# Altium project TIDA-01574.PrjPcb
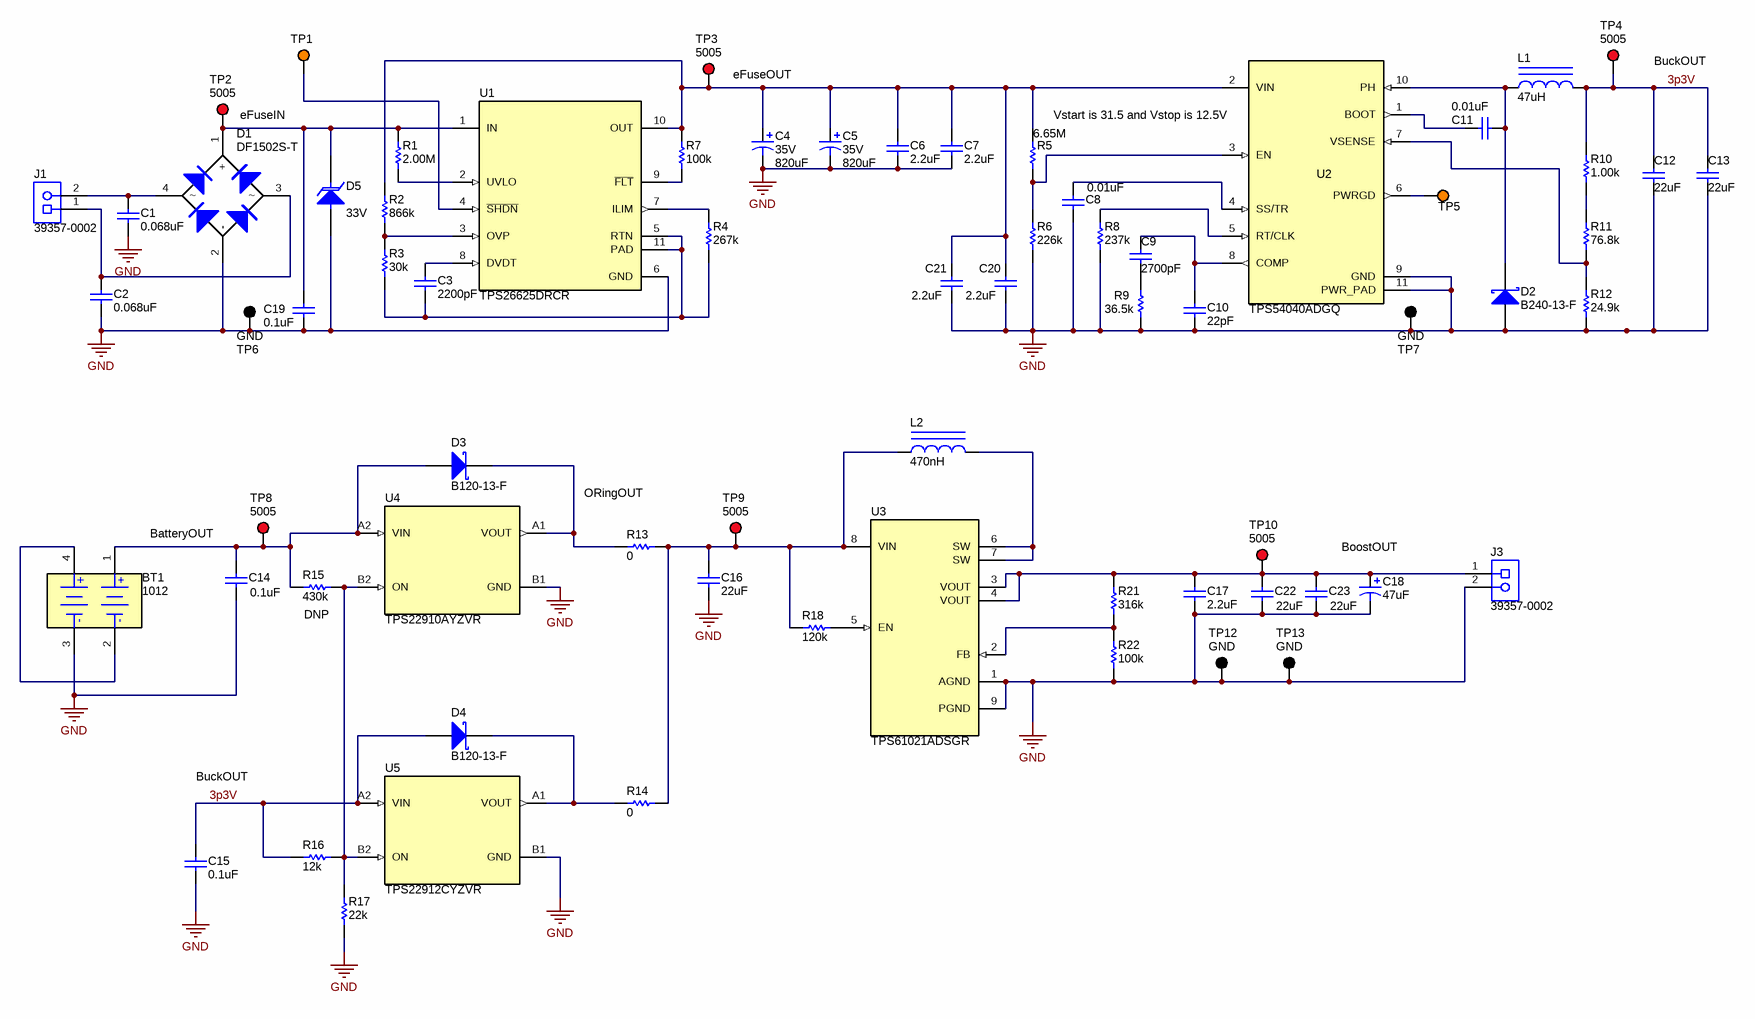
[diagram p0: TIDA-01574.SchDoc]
CopyrightYear: 2017; PCB_Layout: Mansur; PCB_Rev: E1; PRJ_Customer: Public Release; PRJ_Engineer: Karikalan Selvaraj; PRJ_Number: TIDA-01574; PRJ_Title: Power Stage Reference Design for Power Stealing Thermostat; SCH_Rev: E1; TechSupport: http://www.ti.com/support; TID: TIDA-01574
3 sheets, 83 parts. Net scope: global (net labels, ports and power ports of the same name join across sheets).
Board file: TIDA-01574.PcbDoc
Sheets:
  TIDA-01574.SchDoc
  TIDA-01574_CoverSheet.SchDoc
  TIDA-01574_Hardware.SchDoc

## Sheet TIDA-01574.SchDoc
size 431 x 279 mm; Date: Not shown in title block; ApprovedBy: Not shown in title block; CheckedBy: Not shown in title block; Author: Not shown in title block; CompanyName: Not shown in title block; Engineer: Not shown in title block; Organization: Not shown in title block; Address1: Not shown in title block; Address2: Not shown in title block; Address3: Not shown in title block; Address4: Not shown in title block; DocumentNumber: 1; Revision: Use project parameter SCH_Rev; SheetNumber: 2; SheetTotal: 3; PageSetup: Record=PageOptions¦CenterHorizontal=True¦CenterVertical=True¦PrintScale=1.00¦XCorrection=1.00¦YCorrection=1.00¦PrintKind=0¦BorderSize=5000000¦LeftOffset=0¦BottomOffset=0¦Orientation=2¦PaperLength=1000¦PaperWidth=1000¦Scale=100¦PaperSource=15¦PrintQuality=600¦MediaType=1¦DitherType=10¦PaperKind=Letter¦PrintScaleMode=1

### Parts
BT1  1012  [Keystone_1012]
C1  ValueDisplayed: 0.068uF  [0603]  (hidden comment: C1608X7S2A683K080AB)
C2  ValueDisplayed: 0.068uF  [0603]  (hidden comment: C1608X7S2A683K080AB)
C3  ValueDisplayed: 2200pF  [0603]  (hidden comment: C0603C222K5RAC)
C4  VDC_V: 35V  ValueDisplayed: 820uF  [TP_1250x2500]  (hidden comment: EEU-TP1V821B)
C5  VDC_V: 35V  ValueDisplayed: 820uF  [TP_1250x2500]  (hidden comment: EEU-TP1V821B)
C6  ValueDisplayed: 2.2uF  [1206_180]  (hidden comment: GRM31CR71H225KA88L)
C7  ValueDisplayed: 2.2uF  [1206_180]  (hidden comment: GRM31CR71H225KA88L)
C8  ValueDisplayed: 0.01uF  [0603]  (hidden comment: C0603C103J3GECAUTO)
C9  ValueDisplayed: 2700pF  [0603]  (hidden comment: GRM188R71E272KA01D)
C10  ValueDisplayed: 22pF  [0603]  (hidden comment: 06035A220JAT2A)
C11  ValueDisplayed: 0.01uF  [0603]  (hidden comment: C0603C103J3GECAUTO)
C12  ValueDisplayed: 22uF  [1206]  (hidden comment: C3216X5R0J226M085AC)
C13  ValueDisplayed: 22uF  [1206]  (hidden comment: C3216X5R0J226M085AC)
C14  ValueDisplayed: 0.1uF  [0603]  (hidden comment: 0603YC104JAT2A)
C15  ValueDisplayed: 0.1uF  [0603]  (hidden comment: 0603YC104JAT2A)
C16  ValueDisplayed: 22uF  [0805_HV]  (hidden comment: GRM21BR61A226ME44L)
C17  ValueDisplayed: 2.2uF  [0805_HV]  (hidden comment: C2012X7R1C225K125AB)
C18  ValueDisplayed: 47uF  [CC_CASEC]  (hidden comment: 594D476X0016C2T)
C19  ValueDisplayed: 0.1uF  [0805_HV]  (hidden comment: GRM21BR72A104KAC4L)
C20  ValueDisplayed: 2.2uF  [1206_180]  (hidden comment: GRM31CR71H225KA88L)
C21  ValueDisplayed: 2.2uF  [1206_180]  (hidden comment: GRM31CR71H225KA88L)
C22  ValueDisplayed: 22uF  [0805_HV]  (hidden comment: GRM21BR61A226ME44L)
C23  ValueDisplayed: 22uF  [0805_HV]  (hidden comment: GRM21BR61A226ME44L)
D1  DF1502S-T  [DF-S]
D2  B240-13-F  [SMB]
D3  B120-13-F  [SMA]
D4  B120-13-F  [SMA]
D5  value 33V  [SMB]  (hidden comment: SMBJ33A-13-F)
J1  39357-0002  [MOLEX_39357-0002]
J3  39357-0002  [MOLEX_39357-0002]
L1  ValueDisplayed: 47uH  [MSS1048]  (hidden comment: MSS1048-473MLB)
L2  ValueDisplayed: 470nH  [XFL4015]  (hidden comment: XFL4015-471MEC)
R1  ValueDisplayed: 2.00M  [0603]  (hidden comment: RC0603FR-072ML)
R2  ValueDisplayed: 866k  [0603]  (hidden comment: CRCW0603866KFKEA)
R3  ValueDisplayed: 30k  [0603]  (hidden comment: CRCW060330K0JNEA)
R4  ValueDisplayed: 267k  [0603]  (hidden comment: RT0603BRD07267KL)
R5  ValueDisplayed: 6.65M  [0603]  (hidden comment: CRCW06036M65FKEA)
R6  ValueDisplayed: 226k  [0603]  (hidden comment: RC0603FR-07226KL)
R7  ValueDisplayed: 100k  [0603]  (hidden comment: CRCW0603100KJNEA)
R8  ValueDisplayed: 237k  [0603]  (hidden comment: CRCW0603237KFKEA)
R9  ValueDisplayed: 36.5k  [0603]  (hidden comment: CRCW060336K5FKEA)
R10  ValueDisplayed: 1.00k  [0603]  (hidden comment: CRCW06031K00FKEA)
R11  ValueDisplayed: 76.8k  [0603]  (hidden comment: CRCW060376K8FKEA)
R12  ValueDisplayed: 24.9k  [0603]  (hidden comment: CRCW060324K9FKEA)
R13  ValueDisplayed: 0  [0805_HV]  (hidden comment: CRCW08050000Z0EA)
R14  ValueDisplayed: 0  [0805_HV]  (hidden comment: CRCW08050000Z0EA)
R15  ValueDisplayed: 430k  [0603]  (hidden comment: CRCW0603430KJNEA)
R16  ValueDisplayed: 12k  [0603]  (hidden comment: CRCW060312K0JNEA)
R17  ValueDisplayed: 22k  [0603]  (hidden comment: CRCW060322K0JNEA)
R18  ValueDisplayed: 120k  [0603]  (hidden comment: CRCW0603120KJNEA)
R21  ValueDisplayed: 316k  [0603]  (hidden comment: CRCW0603316KFKEA)
R22  ValueDisplayed: 100k  [0603]  (hidden comment: CRCW0603100KFKEA)
TP1  5008  [Keystone5008]  (value not drawn)
TP2  5005  [Keystone5005]
TP3  5005  [Keystone5005]
TP4  5005  [Keystone5005]
TP5  5008  [Keystone5008]  (value not drawn)
TP6  GND  [Keystone5006]
TP7  GND  [Keystone5006]
TP8  5005  [Keystone5005]
TP9  5005  [Keystone5005]
TP10  5005  [Keystone5005]
TP12  GND  [Keystone5006]
TP13  GND  [Keystone5006]
U1  TPS26625DRCR  [DRC0010J]
U2  TPS54040ADGQ  [DGQ0010D_N]
U3  TPS61021ADSGR  [DSG0008A]
U4  TPS22910AYZVR  [YZV0004ADAD]
U5  TPS22912CYZVR  [YZV0004ADAD]

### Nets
GND: BT1.3(-) C1.2 C2.2 C4.2(-) C5.2(-) C6.2 C7.2 C8.2 C10.2 C12.2 C13.2 C14.2 C15.2 C16.2 C17.2 C18.2(-) C19.2 C20.2 C21.2 C22.2 C23.2 D1.2(-) D2.2(A) D5.2(A) J3.2 R6.1 R8.1 R9.1 R12.1 R17.1 R22.1 TP6.1 TP7.1 TP12.1 TP13.1 U1.6(GND) U2.9(GND) U2.11(PWR_PAD) U3.1(AGND) U3.9(PGND) U4.B1(GND) U5.B1(GND)
3p3V: C12.1 C13.1 C15.1 D4.2(A) L1.2 R10.2 R16.1 TP4.1 U5.A2(VIN)
NetBT1_1: BT1.1(+) C14.1 D3.2(A) R15.1 TP8.1 U4.A2(VIN)
NetBT1_2: BT1.2(-) BT1.4(+)
NetC1_1: C1.1 D1.4 J1.2
NetC2_1: C2.1 D1.3 J1.1
NetC3_1: C3.1 U1.8(DVDT)
NetC3_2: C3.2 R3.1 R4.1 U1.5(RTN) U1.11(PAD)
NetC4_1: C4.1(+) C5.1(+) C6.1 C7.1 C20.1 C21.1 R2.2 R5.2 R7.2 TP3.1 U1.10(OUT) U2.2(VIN)
NetC8_1: C8.1 U2.4(SS/TR)
NetC9_1: C9.1 C10.1 U2.8(COMP)
NetC9_2: C9.2 R9.2
NetC11_1: C11.1 D2.1(K) L1.1 U2.10(PH)
NetC11_2: C11.2 U2.1(BOOT)
NetC16_1: C16.1 L2.1 R13.2 R14.2 R18.1 TP9.1 U3.8(VIN)
NetC17_1: C17.1 C18.1(+) C22.1 C23.1 J3.1 R21.2 TP10.1 U3.3(VOUT) U3.4(VOUT)
NetC19_1: C19.1 D1.1(+) D5.1(K) R1.2 TP2.1 U1.1(IN)
NetD3_1: D3.1(K) R13.1 U4.A1(VOUT)
NetD4_1: D4.1(K) R14.1 U5.A1(VOUT)
NetL2_2: L2.2 U3.6(SW) U3.7(SW)
NetR1_1: R1.1 U1.2(UVLO)
NetR2_1: R2.1 R3.2 U1.3(OVP)
NetR4_2: R4.2 U1.7(ILIM)
NetR5_1: R5.1 R6.2 U2.3(EN)
NetR7_1: R7.1 U1.9(~{FLT})
NetR8_2: R8.2 U2.5(RT/CLK)
NetR10_1: R10.1 R11.2
NetR11_1: R11.1 R12.2 U2.7(VSENSE)
NetR15_2: R15.2 R16.2 R17.2 U4.B2(ON) U5.B2(ON)
NetR18_2: R18.2 U3.5(EN)
NetR21_1: R21.1 R22.2 U3.2(FB)
NetTP1_1: TP1.1 U1.4(~{SHDN})
NetTP5_1: TP5.1 U2.6(PWRGD)

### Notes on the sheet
- (near TP3) eFuseOUT
- (near TP4) BuckOUT
- (near TP2) eFuseIN
- (near U2) Vstart is 31.5 and Vstop is 12.5V
- BatteryOUT
- (near R13) ORingOUT
- BoostOUT
- (near R15) DNP
- BuckOUT

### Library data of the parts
BT1 = CMP-0003769-1: Battery holder for 2AA, SMD; Manufacturer: Keystone
C1 C2 = CMP-0007061-4: CAP, CERM, 0.068 uF, 100 V, +/- 10%, X7S, 0603; Manufacturer: TDK; Polarized: N; U/M: EA; Cap_F: 68nF; ESR_ohm: 0.074084; Value1: 0.074084 ohm; VDC_V: 100V; IRMS_A: 6.1909dA; TaMin_C: -55°C; TaMax_C: 125°C; SizeArea_mm2: 1.28; SizeAreaWB_mm2: 4.68; SizeX_mm: 1.6; SizeY_mm: 0.8; SizeZ_mm: 1; AEC Category: Q200
C3 = CMP-0006897-4: CAP, CERM, 2200 pF, 50 V, +/- 10%, X7R, 0603; Manufacturer: Kemet; Polarized: N; Value: 2200pF; U/M: EA; Cap_F: 2.2nF; Value1: Unknown; VDC_V: 50V; TaMin_C: -55°C; TaMax_C: 125°C; SizeArea_mm2: 1.28; SizeAreaWB_mm2: 4.68; SizeX_mm: 1.6; SizeY_mm: 0.8; SizeZ_mm: 1; AEC Category: Q200
C4 C5 = CMP-0010356-2: CAP, AL, 820 uF, 35 V, +/- 20%, 0.03 ohm, AEC-Q200 Grade 1, TH; Manufacturer: Panasonic; TaMin_C: -40°C; ESR_ohm: 0.03; Polarized: Y; SizeAreaWB_mm2: 210.25; U/M: EA; Value: 820uF; TaMax_C: 135°C; SizeZ_mm: 27; SizeX_mm: 12.5; Cap_Case: 12.5x25mm; SizeArea_mm2: 156.25; CompType: Capacitor; Cap_F: 820µF; IRMS_A: 2.18A; AEC Grade: 1; AEC Category: Q200
C6 C7 C20 C21 = CMP-0008968-2: CAP, CERM, 2.2 uF, 50 V, +/- 10%, X7R, 1206; Manufacturer: MuRata; Polarized: N; Value: 2.2uF; U/M: EA; Cap_F: 2.2µF; Value1: Unknown; VDC_V: 50V; TaMin_C: -55°C; TaMax_C: 125°C; Cap_Case: 1206; SizeArea_mm2: 5.12; SizeAreaWB_mm2: 10.92; SizeX_mm: 3.2; SizeY_mm: 1.6; SizeZ_mm: 1.8; AEC Category: Q200
C8 C11 = CMP-0006849-4: CAP, CERM, 0.01 uF, 25 V, +/- 5%, C0G/NP0, AEC-Q200 Grade 1, 0603; Manufacturer: Kemet; Polarized: N; Value: 0.01uF; U/M: EA; Cap_F: 10nF; Value1: Unknown; VDC_V: 25V; TaMin_C: -55°C; TaMax_C: 125°C; SizeArea_mm2: 1.28; SizeAreaWB_mm2: 4.68; SizeX_mm: 1.6; SizeY_mm: 0.8; SizeZ_mm: 1; AEC Category: Q200; AEC Qualified: Y
C9 = CMP-0007416-5: CAP, CERM, 2700 pF, 25 V, +/- 10%, X7R, 0603; Manufacturer: MuRata; Polarized: N; Value: 2700pF; U/M: EA; Cap_F: 2.7nF; Value1: Unknown; VDC_V: 25V; TaMin_C: -55°C; TaMax_C: 125°C; SizeArea_mm2: 1.28; SizeAreaWB_mm2: 4.68; SizeX_mm: 1.6; SizeY_mm: 0.8; SizeZ_mm: 1; AEC Category: Q200
C10 = CMP-0006775-4: CAP, CERM, 22 pF, 50 V, +/- 5%, C0G/NP0, 0603; Manufacturer: AVX; Polarized: N; Value: 22pF; U/M: EA; ESR_ohm: 2.59d; Value1: 0.259 ohm; VDC_V: 50V; TaMin_C: -55°C; TaMax_C: 125°C; SizeArea_mm2: 1.28; SizeAreaWB_mm2: 4.68; SizeX_mm: 1.6; SizeY_mm: 0.8; SizeZ_mm: 1; AEC Category: Q200
C12 C13 = CMP-0008648-2: CAP, CERM, 22 uF, 6.3 V, +/- 20%, X5R, 1206; Manufacturer: TDK; Polarized: N; Value: 22uF; U/M: EA; Cap_F: 22µF; ESR_ohm: 2m; Value1: 0.002 ohm; VDC_V: 6.3V; IRMS_A: 3.62A; TaMin_C: -55°C; TaMax_C: 85°C; SizeArea_mm2: 5.12; SizeAreaWB_mm2: 10.92; SizeX_mm: 3.2; SizeY_mm: 1.6; SizeZ_mm: 1.35; AEC Category: Q200
C14 C15 = CMP-0006808-4: CAP, CERM, 0.1 uF, 16 V, +/- 5%, X7R, 0603; Manufacturer: AVX; Polarized: N; Value: 0.1uF; U/M: EA; Cap_F: 100nF; ESR_ohm: 0.039; Value1: 0.039 ohm; VDC_V: 16V; TaMin_C: -55°C; TaMax_C: 125°C; SizeArea_mm2: 1.28; SizeAreaWB_mm2: 4.68; SizeX_mm: 1.6; SizeY_mm: 0.8; SizeZ_mm: 1; AEC Category: Q200
C16 = CMP-0008286-2: CAP, CERM, 22 uF, 10 V, +/- 20%, X5R, 0805; Manufacturer: MuRata; Polarized: N; Value: 22uF; U/M: EA; Cap_F: 22µF; Value1: Unknown; VDC_V: 10V; TaMin_C: -55°C; TaMax_C: 85°C; Cap_Case: 0805; SizeArea_mm2: 2.5; SizeAreaWB_mm2: 6.75; SizeX_mm: 2; SizeY_mm: 1.25; SizeZ_mm: 1.45; AEC Category: Q200
C17 = CMP-0007867-2: CAP, CERM, 2.2 uF, 16 V, +/- 10%, X7R, 0805; Manufacturer: TDK; Polarized: N; Value: 2.2uF; U/M: EA; Cap_F: 2.2µF; ESR_ohm: 4.9m; Value1: 0.0049 ohm; VDC_V: 16V; TaMin_C: -55°C; TaMax_C: 125°C; Cap_Case: 0805; SizeArea_mm2: 2.5; SizeAreaWB_mm2: 6.75; SizeX_mm: 2; SizeY_mm: 1.25; SizeZ_mm: 1.45; AEC Category: Q200
C18 = CMP-0012004-2: CAP, TA, 47 uF, 16 V, +/- 20%, 0.11 ohm, SMD; Manufacturer: Vishay-Sprague; Polarized: Y; CompType: Capacitor; Value: 47uF; U/M: EA; Cap_F: 47µF; VDC_V: 16V; ESR_ohm: 1.1d; IRMS_A: 1A; TaMin_C: -55°C; TaMax_C: 85°C; Cap_Case: C; SizeAreaWB_mm2: 47.32; SizeArea_mm2: 22.72; SizeX_mm: 7.1; SizeY_mm: 3.2; SizeZ_mm: 2.5; AEC Category: Q200
C19 = CMP-0008363-2: CAP, CERM, 0.1 uF, 100 V, +/- 10%, X7R, 0805; Manufacturer: MuRata; Polarized: N; Value: 0.1uF; U/M: EA; Cap_F: 100nF; Value1: Unknown; VDC_V: 100V; TaMin_C: -55°C; TaMax_C: 125°C; Cap_Case: 0805; SizeArea_mm2: 2.5; SizeAreaWB_mm2: 6.75; SizeX_mm: 2; SizeY_mm: 1.25; SizeZ_mm: 1.45; AEC Category: Q200
C22 C23 = CMP-0008286-2: CAP, CERM, 22 uF, 10 V, +/- 20%, X5R, 0805; Manufacturer: MuRata; TaMin_C: -55°C; Polarized: N; SizeAreaWB_mm2: 6.75; Value1: Unknown; U/M: EA; Value: 22uF; TaMax_C: 85°C; SizeZ_mm: 1.45; SizeX_mm: 2; SizeY_mm: 1.25; Cap_Case: 0805; Value2: 10V; SizeArea_mm2: 2.5; CompType: Capacitor; Cap_F: 22µF; AEC Category: Q200
D1 = CMP-0029207-2: Diode, Switching-Bridge, 200 V, 1.5 A, DF-S; Manufacturer: Diodes Inc.; U/M: EA; Vf_V: 1.1V; Value: 200V; Value1: 1.5A; TJmax_C: 150°C; SizeAreaWB_mm2: 98.794; SizeArea_mm2: 62.974; SizeX_mm: 7.4; SizeY_mm: 8.51; SizeZ_mm: 3.4; AEC Category: Q101; Green_Lifecycle: Not Set; Green_REACh: Incomplete
D2 = CMP-0028402-1: Diode, Schottky, 40 V, 2 A, SMB; Manufacturer: Diodes Inc.; Io_A: 2A; Green_Lifecycle: Not Set; SizeAreaWB_mm2: 44.156; Vr_V: 40V; Green_REACh: Incomplete; TJmax_C: 150°C; U/M: EA; Value: 40V; SizeZ_mm: 2.6; SizeX_mm: 5.6; SizeY_mm: 3.81; Vf_V: 5dV; Value2: 0.5V; SizeArea_mm2: 21.336; AEC Category: Q101; RJC_CperW: 20
D3 D4 = CMP-0028374-1: Diode, Schottky, 20 V, 1 A, SMA; Manufacturer: Diodes Inc.; U/M: EA; Vf_V: 5dV; Value: 20V; Value1: 1A; Value2: 0.5V; TJmax_C: 150°C; RJC_CperW: 20; SizeAreaWB_mm2: 37.3428; SizeArea_mm2: 16.3228; SizeX_mm: 5.59; SizeY_mm: 2.92; SizeZ_mm: 2.87; AEC Category: Q101; Green_Lifecycle: Active; Green_REACh: Passed
D5 = CMP-0005563-2: Diode, TVS, Uni, 33 V, 53.3 Vc, SMB; Manufacturer: Diodes Inc.; Power_W: 5W; SizeAreaWB_mm2: 44.156; U/M: EA; SizeZ_mm: 2.6; SizeX_mm: 5.6; SizeY_mm: 3.81; SizeArea_mm2: 21.336; AEC Category: Q101
J1 J3 = CMP-0055341-1: Terminal Block, 3.5 mm, 2x1, Tin, TH; Manufacturer: Molex; Green_Lifecycle: Not Set; Green_REACh: Incomplete; CNHeader: FALSE; CT: TRUE
L1 = CMP-0061449-2: Inductor, Shielded Drum Core, Ferrite, 47 uH, 2.2 A, 0.13 ohm, SMD; Manufacturer: Coilcraft; Isat: 2.2A @ 30% inductance drop; Irms: 2.42A @ 40C rise; Green_Lifecycle: Not Set; SizeAreaWB_mm2: 146.4; DCR_ohm: 1.3d; Green_REACh: Incomplete; Value: 47uH; Imax_A: 2.2A; SizeZ_mm: 4.8; SizeX_mm: 10.2; SizeY_mm: 10; SizeArea_mm2: 102; Ind_H: 47µH; AEC Category: Q200
L2 = CMP-0061147-1: Inductor, Shielded, Composite, 470 nH, 3.5 A, 0.0076 ohm, SMD; Manufacturer: Coilcraft; Isat: 3.5A @ 10% inductance drop; Irms: 9.1A @ 20C rise; Green_Lifecycle: Not Set; SizeAreaWB_mm2: 28.09; DCR_ohm: 7.6m; Green_REACh: Incomplete; Value: 470nH; Imax_A: 3.5A; SizeZ_mm: 1.6; SizeX_mm: 4.3; SizeArea_mm2: 18.49; AEC Category: Q200
R1 = CMP-0023004-2: RES, 2.00 M, 1%, 0.1 W, 0603; Manufacturer: Yageo America; Value: 2.00Meg; Res_ohm: 2M; Value_Code: 2M00; Power_W: 100mW; Value2: 0.1W; VDC_V: 150V; TempCo: 200 ppm/C; SizeArea_mm2: 1.28; SizeX_mm: 1.6; SizeY_mm: 0.8; SizeZ_mm: 1; EIA_Code: E96; U/M: EA; AEC Category: Q200
R2 = CMP-0022626-2: RES, 866 k, 1%, 0.1 W, 0603; Manufacturer: Vishay-Dale; Value: 866k; Power_W: 100mW; Value2: 0.1W; VDC_V: 75V; TempCo: 100 ppm/C; SizeArea_mm2: 1.28; SizeX_mm: 1.6; SizeY_mm: 0.8; SizeZ_mm: 1; EIA_Code: E96; U/M: EA; AEC Category: Q200
R3 = CMP-0025782-3: RES, 30 k, 5%, 0.1 W, 0603; Manufacturer: Vishay-Dale; Value: 30k; Value_Code: 30k0; Power_W: 100mW; Value2: 0.1W; VDC_V: 75V; TempCo: 200 ppm/C; SizeArea_mm2: 1.28; SizeX_mm: 1.6; SizeY_mm: 0.8; SizeZ_mm: 1; EIA_Code: E24; U/M: EA; AEC Category: Q200
R4 = CMP-0024012-3: RES, 267 k, 0.1%, 0.1 W, 0603; Manufacturer: Yageo America; Value: 267k; Power_W: 100mW; Value2: 0.1W; VDC_V: 75V; TempCo: 25 ppm/C; SizeArea_mm2: 1.28; SizeX_mm: 1.6; SizeY_mm: 0.8; SizeZ_mm: 1; EIA_Code: E192; U/M: EA; AEC Category: Q200
R5 = CMP-0022569-4: RES, 6.65 M, 1%, 0.1 W, AEC-Q200 Grade 0, 0603; Manufacturer: Vishay-Dale; Value: 6.65Meg; Value_Code: 6M65; Power_W: 100mW; Value2: 0.1W; VDC_V: 75V; TempCo: 100 ppm/C; SizeArea_mm2: 1.28; SizeX_mm: 1.6; SizeY_mm: 0.8; SizeZ_mm: 1; EIA_Code: E96; AEC Category: Q200; AEC Qualified: Y; AEC Grade: 0
R6 = CMP-0022921-2: RES, 226 k, 1%, 0.1 W, 0603; Manufacturer: Yageo America; Value: 226k; Power_W: 100mW; Value2: 0.1W; VDC_V: 150V; TempCo: 200 ppm/C; SizeArea_mm2: 1.28; SizeX_mm: 1.6; SizeY_mm: 0.8; SizeZ_mm: 1; EIA_Code: E96; U/M: EA; AEC Category: Q200
R7 = CMP-0025698-3: RES, 100 k, 5%, 0.1 W, 0603; Manufacturer: Vishay-Dale; Value: 100k; Power_W: 100mW; Value2: 0.1W; VDC_V: 75V; TempCo: 200 ppm/C; SizeArea_mm2: 1.28; SizeX_mm: 1.6; SizeY_mm: 0.8; SizeZ_mm: 1; EIA_Code: E24; U/M: EA; AEC Category: Q200
R8 = CMP-0022226-3: RES, 237 k, 1%, 0.1 W, 0603; Manufacturer: Vishay-Dale; Value: 237k; Power_W: 100mW; Value2: 0.1W; VDC_V: 75V; TempCo: 100 ppm/C; SizeArea_mm2: 1.28; SizeX_mm: 1.6; SizeY_mm: 0.8; SizeZ_mm: 1; EIA_Code: E96; U/M: EA; AEC Category: Q200
R9 = CMP-0022356-3: RES, 36.5 k, 1%, 0.1 W, 0603; Manufacturer: Vishay-Dale; Value: 36.5k; Value_Code: 36k5; Power_W: 100mW; Value2: 0.1W; VDC_V: 75V; TempCo: 100 ppm/C; SizeArea_mm2: 1.28; SizeX_mm: 1.6; SizeY_mm: 0.8; SizeZ_mm: 1; EIA_Code: E96; U/M: EA; AEC Category: Q200
R10 = CMP-0022109-4: RES, 1.00 k, 1%, 0.1 W, 0603; Manufacturer: Vishay-Dale; Value: 1.00k; Res_ohm: 1k; Value_Code: 1k00; Power_W: 100mW; Value2: 0.1W; VDC_V: 75V; TempCo: 100 ppm/C; SizeArea_mm2: 1.28; SizeX_mm: 1.6; SizeY_mm: 0.8; SizeZ_mm: 1; EIA_Code: E96; U/M: EA; AEC Category: Q200
R11 = CMP-0022593-3: RES, 76.8 k, 1%, 0.1 W, 0603; Manufacturer: Vishay-Dale; Value: 76.8k; Value_Code: 76k8; Power_W: 100mW; Value2: 0.1W; VDC_V: 75V; TempCo: 100 ppm/C; SizeArea_mm2: 1.28; SizeX_mm: 1.6; SizeY_mm: 0.8; SizeZ_mm: 1; EIA_Code: E96; U/M: EA; AEC Category: Q200
R12 = CMP-0022237-3: RES, 24.9 k, 1%, 0.1 W, 0603; Manufacturer: Vishay-Dale; Value: 24.9k; Value_Code: 24k9; Power_W: 100mW; Value2: 0.1W; VDC_V: 75V; TempCo: 100 ppm/C; SizeArea_mm2: 1.28; SizeX_mm: 1.6; SizeY_mm: 0.8; SizeZ_mm: 1; EIA_Code: E96; U/M: EA; AEC Category: Q200
R13 R14 = CMP-0020442-2: RES, 0, 5%, 0.125 W, 0805; Manufacturer: Vishay-Dale; Value: 0; Value_Code: 0000; Power_W: 125mW; Value2: 0.125W; VDC_V: 150V; TempCo: 200 ppm/C; SizeArea_mm2: 2.5; SizeX_mm: 2; SizeY_mm: 1.25; SizeZ_mm: 1.45; EIA_Code: E24; U/M: EA; AEC Category: Q200
R15 = CMP-0025808-3: RES, 430 k, 5%, 0.1 W, 0603; Manufacturer: Vishay-Dale; Value: 430k; Power_W: 100mW; Value2: 0.1W; VDC_V: 75V; TempCo: 200 ppm/C; SizeArea_mm2: 1.28; SizeX_mm: 1.6; SizeY_mm: 0.8; SizeZ_mm: 1; EIA_Code: E24; U/M: EA; AEC Category: Q200
R16 = CMP-0025711-3: RES, 12 k, 5%, 0.1 W, 0603; Manufacturer: Vishay-Dale; Value: 12k; Value_Code: 12k0; Power_W: 100mW; Value2: 0.1W; VDC_V: 75V; TempCo: 200 ppm/C; SizeArea_mm2: 1.28; SizeX_mm: 1.6; SizeY_mm: 0.8; SizeZ_mm: 1; EIA_Code: E24; U/M: EA; AEC Category: Q200
R17 = CMP-0025757-3: RES, 22 k, 5%, 0.1 W, 0603; Manufacturer: Vishay-Dale; Power_W: 100mW; TempCo: 200 ppm/C; Value_Code: 22k0; U/M: EA; Value: 22k; EIA_Code: E24; SizeX_mm: 1.6; SizeY_mm: 0.8; SizeZ_mm: 1; Value2: 0.1W; SizeArea_mm2: 1.28; CompType: Resistor; VDC_V: 75V; AEC Category: Q200
R18 = CMP-0025709-3: RES, 120 k, 5%, 0.1 W, 0603; Manufacturer: Vishay-Dale; Value: 120k; Power_W: 100mW; Value2: 0.1W; VDC_V: 75V; TempCo: 200 ppm/C; SizeArea_mm2: 1.28; SizeX_mm: 1.6; SizeY_mm: 0.8; SizeZ_mm: 1; EIA_Code: E24; U/M: EA; AEC Category: Q200
R21 = CMP-0022328-3: RES, 316 k, 1%, 0.1 W, 0603; Manufacturer: Vishay-Dale; Power_W: 100mW; TempCo: 100 ppm/C; U/M: EA; Value: 316k; EIA_Code: E96; SizeX_mm: 1.6; SizeY_mm: 0.8; SizeZ_mm: 1; Value2: 0.1W; SizeArea_mm2: 1.28; CompType: Resistor; VDC_V: 75V; AEC Category: Q200
R22 = CMP-0021990-3: RES, 100 k, 1%, 0.1 W, 0603; Manufacturer: Vishay-Dale; Power_W: 100mW; TempCo: 100 ppm/C; U/M: EA; Value: 100k; EIA_Code: E96; SizeX_mm: 1.6; SizeY_mm: 0.8; SizeZ_mm: 1; Value2: 0.1W; SizeArea_mm2: 1.28; CompType: Resistor; VDC_V: 75V; AEC Category: Q200
TP1 TP5 = CMP-0055145-1: Test Point, Compact, Orange, TH; Manufacturer: Keystone; ContactFinish: Silver; Green_Lifecycle: Active; Green_REACh: Passed; CNHeader: FALSE; CT: TRUE
TP2-TP4 TP8-TP10 = CMP-0055142-1: Test Point, Compact, Red, TH; Manufacturer: Keystone; ContactFinish: Silver; Green_Lifecycle: Active; Green_REACh: Passed; CNHeader: FALSE; CT: TRUE
TP6 TP7 TP12 TP13 = CMP-0055143-1: Test Point, Compact, Black, TH; Manufacturer: Keystone; ContactFinish: Silver; Green_Lifecycle: Active; Green_REACh: Passed; CNHeader: FALSE; CT: TRUE
U1 = CMP-0013395-4: 7V - 57V, 800mA Industrial eFuse with Integrated Reverse Polarity Protection, DRC0010J (VSON-10); Alternate PartNumber: TPS26625DRCT; Manufacturer: Texas Instruments; SizeArea_mm2: 9; SizeAreaWB_mm2: 16; SizeX_mm: 3; SizeZ_mm: 1; CompType: IC; AEC Category: Q200; AEC Qualified: N
U2 = CMP-0067022-2: 3.5V to 42V Input, 0.5A Step-Down Converter with Eco-Mode, DGQ0010D (VSSOP-10); Manufacturer: Texas Instruments; AEC Category: Q200; AEC Qualified: N; CompType: IC; Green_Lifecycle: Active; Green_REACh: Passed; SizeArea_mm2: 14.7; SizeAreaWB_mm2: 23.6; SizeX_mm: 4.9; SizeY_mm: 3.0; SizeZ_mm: 1.1; U/M: EA
U3 = CMP-0074064-2: 3-A Boost Converter with 0.5-V Ultra Low Input Voltage, DSG0008A (WSON-8); Alternate PartNumber: TPS61021ADSGT; Manufacturer: Texas Instruments; SizeZ_mm: 0.8; SizeX_mm: 2.0; SizeArea_mm2: 4.0; CompType: IC; U/M: EA; SizeAreaWB_mm2: 9.0
U4 = CMP-0066643-1: 5.5V, 2A, 61mΩ Active-Low Load Switch With Reverse Current Protection, YZV0004ADAD (DSBGA-4); Alternate PartNumber: TPS22910AYZVT; Alternate Manufacturer: Texas Instruments; Green_Lifecycle: Active; SizeAreaWB_mm2: 5.0625; Green_REACh: Passed; U/M: EA; SizeZ_mm: 0.5; SizeX_mm: 1.25; SizeArea_mm2: 1.5625; CompType: IC
U5 = CMP-0066644-1: 5.5V, 2A, 61mΩ Load Switch With Reverse Current Protection, YZV0004ADAD (DSBGA-4); Alternate PartNumber: TPS22912CYZVT; Alternate Manufacturer: Texas Instruments; Green_Lifecycle: Active; SizeAreaWB_mm2: 5.0625; Green_REACh: Passed; U/M: EA; SizeZ_mm: 0.5; SizeX_mm: 1.25; SizeArea_mm2: 1.5625; CompType: IC

## Sheet TIDA-01574_CoverSheet.SchDoc
size 431 x 279 mm; Date: Not shown in title block; ApprovedBy: Not shown in title block; CheckedBy: Not shown in title block; Author: Not shown in title block; CompanyName: Not shown in title block; Engineer: Not shown in title block; Organization: Not shown in title block; Address1: Not shown in title block; Address2: Not shown in title block; Address3: Not shown in title block; Address4: Not shown in title block; DocumentNumber: 1; Revision: Use project parameter SCH_Rev; SheetNumber: 1; SheetTotal: 3; PageSetup: Record=PageOptions¦CenterHorizontal=True¦CenterVertical=True¦PrintScale=1.00¦XCorrection=1.00¦YCorrection=1.00¦PrintKind=0¦BorderSize=5000000¦LeftOffset=0¦BottomOffset=0¦Orientation=2¦PaperLength=1000¦PaperWidth=1000¦Scale=100¦PaperSource=15¦PrintQuality=600¦MediaType=1¦DitherType=10¦PaperKind=Letter¦PrintScaleMode=1
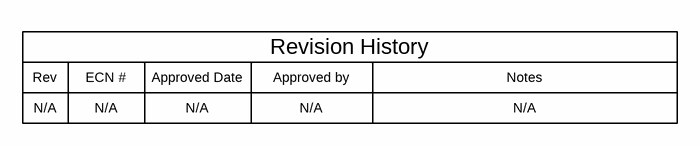
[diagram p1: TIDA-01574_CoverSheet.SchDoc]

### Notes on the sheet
- Rev
- N/A
- ECN #
- Approved Date
- Approved by
- Revision History
- Notes

## Sheet TIDA-01574_Hardware.SchDoc
size 431 x 279 mm; Date: Not shown in title block; ApprovedBy: Not shown in title block; CheckedBy: Not shown in title block; Author: Not shown in title block; CompanyName: Not shown in title block; Engineer: Not shown in title block; Organization: Not shown in title block; Address1: Not shown in title block; Address2: Not shown in title block; Address3: Not shown in title block; Address4: Not shown in title block; DocumentNumber: 1; Revision: Use project parameter SCH_Rev; SheetNumber: 3; SheetTotal: 3; PageSetup: Record=PageOptions¦CenterHorizontal=True¦CenterVertical=True¦PrintScale=1.00¦XCorrection=1.00¦YCorrection=1.00¦PrintKind=0¦BorderSize=5000000¦LeftOffset=0¦BottomOffset=0¦Orientation=2¦PaperLength=1000¦PaperWidth=1000¦Scale=100¦PaperSource=15¦PrintQuality=600¦MediaType=1¦DitherType=10¦PaperKind=Letter¦PrintScaleMode=1
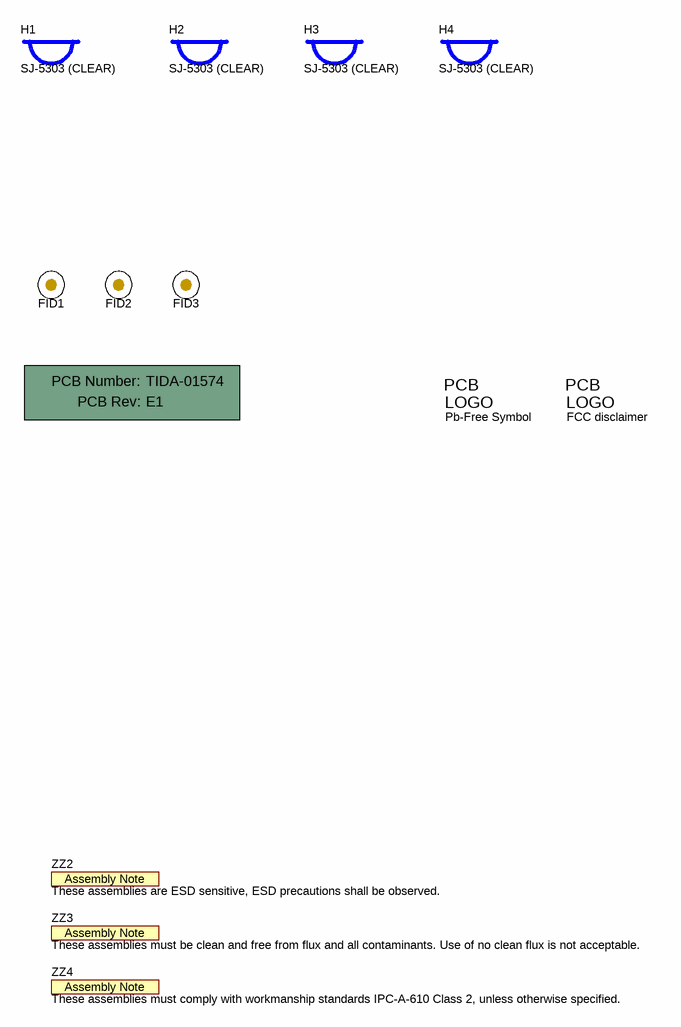
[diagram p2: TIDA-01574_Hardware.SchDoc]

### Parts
!PCB  Printed Circuit Board  (value not drawn)  (mechanical)
FID1  Fiducial  [Fiducial10-20]  (value not drawn)
FID2  Fiducial  [Fiducial10-20]  (value not drawn)
FID3  Fiducial  [Fiducial10-20]  (value not drawn)
H1  SJ-5303 (CLEAR)  [Bumpon_SJ5003Transparent]
H2  SJ-5303 (CLEAR)  [Bumpon_SJ5003Transparent]
H3  SJ-5303 (CLEAR)  [Bumpon_SJ5003Transparent]
H4  SJ-5303 (CLEAR)  [Bumpon_SJ5003Transparent]
Logo2  Pb-Free Symbol  [Pb-Free_Overlay_Small]  (no BOM)
Logo3  FCC disclaimer  [FCC_disclaimer]  (no BOM)
ZZ2  These assemblies are ESD sensitive, ESD precautions shall be observed.  [AssemblyNote]  (no BOM)
ZZ3  These assemblies must be clean and free from flux and all contaminants. Use of no clean flux is not acceptable.  [AssemblyNote]  (no BOM)
ZZ4  These assemblies must comply with workmanship standards IPC-A-610 Class 2, unless otherwise specified.  [AssemblyNote]  (no BOM)

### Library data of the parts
!PCB = CMP-0003618-2: Manufacturer: Any; PartNumber: TIDA-01574
FID1-FID3 = CMP-0077181-1: Fiducial mark.  There is nothing to buy or mount.
H1-H4 = CMP-0003620-1: Bumpon, Hemisphere, 0.44 X 0.20, Clear; Manufacturer: 3M
Logo2 = CMP-0074839-1: SymbolCreator: a0412235; Library Reference: Logo
Logo3 = CMP-0074847-1: FCC_disclaimer; Library Reference: Logo
ZZ2 = CMP-0077236-1
ZZ3 = CMP-0077237-1
ZZ4 = CMP-0077238-1

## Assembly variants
001: not fitted C3 C18 D3 D4 FID1 FID2 FID3 R15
